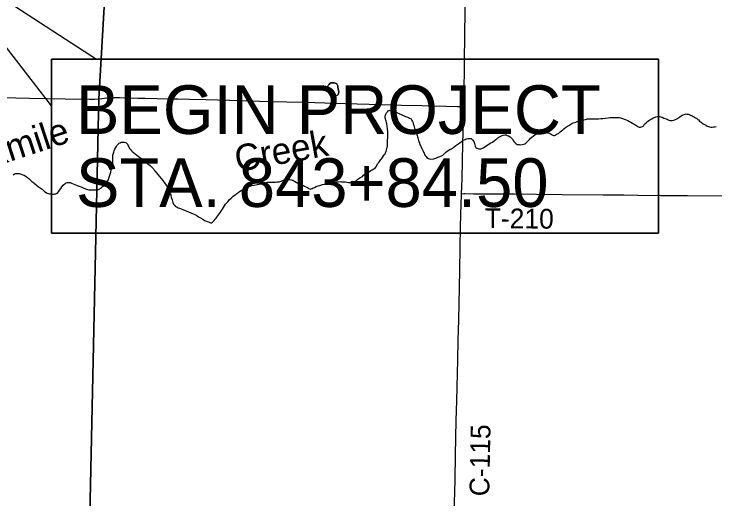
# Model space of a CAD drawing. Extents: x 0 to 64.8, y -5 to 22.
# Drawn here: x 5.41 to 7.424, y 15.884 to 17.279 of the extents above; entities that cross this region are included whole.
import ezdxf

# ---------------------------------------------------------------- set-up
doc = ezdxf.new("R2010")
doc.units = 0
for name, color, linetype in [('GM_X_County_Road', 7, 'Continuous'), ('GM_X_County_Road_Text', 7, 'Continuous'), ('GM_X_Minor_Lake', 7, 'Continuous'), ('GM_X_Minor_Lake_Text', 7, 'Continuous'), ('GM_X_Minor_River', 7, 'Continuous'), ('GM_X_Township', 7, 'Continuous'), ('GM_X_Township_Road', 7, 'Continuous'), ('GM_X_Township_Road_Text', 7, 'Continuous'), ('SH_Masking', 7, 'Continuous'), ('SH_Text', 7, 'Continuous')]:
    doc.layers.add(name, color=color, linetype=linetype)

msp = doc.modelspace()

# ---------------------------------------------------------------- linework, layer by layer
at = {"layer": 'GM_X_County_Road'}
for points in [[(6.7028, 17.0128), (6.7036, 17.0514), (6.7049, 17.1322), (6.7058, 17.2286), (6.7073, 17.328), (6.7091, 17.4368), (6.7108, 17.527), (6.7132, 17.6357), (6.7159, 17.7569), (6.7163, 17.7699)], [(6.6963, 16.7621), (6.6973, 16.8059), (6.6987, 16.8556), (6.6998, 16.9054), (6.7017, 16.9706), (6.7028, 17.011), (6.7028, 17.0128)], [(6.6739, 15.7722), (6.6742, 15.7853), (6.6747, 15.8052), (6.6752, 15.8394), (6.6773, 15.9389), (6.6787, 16.0104), (6.6808, 16.1098), (6.682, 16.1658), (6.685, 16.2838), (6.6863, 16.3398), (6.6877, 16.3988), (6.6897, 16.4921), (6.6909, 16.5418), (6.6922, 16.6071), (6.6934, 16.6661), (6.6942, 16.7034), (6.6962, 16.7593), (6.6963, 16.7621)]]:
    msp.add_lwpolyline(points, dxfattribs=at)
at = {"layer": 'GM_X_Minor_Lake'}
for points in [[(6.3413, 17.0651), (6.3406, 17.0674), (6.3403, 17.0701), (6.34, 17.072), (6.3393, 17.0747), (6.3386, 17.0766), (6.3371, 17.0785), (6.3352, 17.0793), (6.3329, 17.0805), (6.3299, 17.0809), (6.3265, 17.0814), (6.3242, 17.0811), (6.3219, 17.0811), (6.32, 17.0808), (6.3177, 17.0793), (6.315, 17.0767), (6.3126, 17.0737), (6.3118, 17.0715), (6.311, 17.0692), (6.3114, 17.0704), (6.311, 17.0692)], [(6.311, 17.0692), (6.3114, 17.0704), (6.311, 17.0692), (6.3118, 17.0715), (6.3126, 17.0737), (6.315, 17.0767), (6.3177, 17.0793), (6.32, 17.0808), (6.3219, 17.0811), (6.3242, 17.0811), (6.3265, 17.0814), (6.3299, 17.0809), (6.3329, 17.0805), (6.3352, 17.0793), (6.3371, 17.0785), (6.3386, 17.0766), (6.3393, 17.0747), (6.34, 17.072), (6.3403, 17.0701), (6.3406, 17.0674), (6.3413, 17.0651), (6.3417, 17.0632), (6.3424, 17.0598), (6.3427, 17.0579), (6.343, 17.056), (6.3434, 17.0533), (6.3425, 17.051), (6.341, 17.0476), (6.339, 17.0458), (6.3344, 17.044), (6.3317, 17.0429), (6.3291, 17.0426), (6.3271, 17.0423), (6.3241, 17.0427), (6.3218, 17.0431), (6.3192, 17.0447), (6.317, 17.0471), (6.3159, 17.049), (6.3148, 17.052), (6.3137, 17.0551), (6.313, 17.0578), (6.311, 17.0692)], [(6.311, 17.0692), (6.313, 17.0578), (6.3137, 17.0551), (6.3148, 17.052), (6.3159, 17.049), (6.317, 17.0471), (6.3192, 17.0447), (6.3218, 17.0431), (6.3241, 17.0427), (6.3271, 17.0423), (6.3291, 17.0426), (6.3317, 17.0429), (6.3344, 17.044), (6.339, 17.0458), (6.341, 17.0476), (6.3425, 17.051), (6.3434, 17.0533), (6.343, 17.056), (6.3427, 17.0579), (6.3424, 17.0598), (6.3417, 17.0632), (6.3413, 17.0651)]]:
    msp.add_lwpolyline(points, dxfattribs=at)
at = {"layer": 'GM_X_Minor_River'}
for points in [[(6.3763, 16.7946), (6.3809, 16.7945), (6.3843, 16.7944), (6.387, 16.7959), (6.3897, 16.7973), (6.3928, 16.7995), (6.3974, 16.8036), (6.4032, 16.8077), (6.4078, 16.8098), (6.4109, 16.812), (6.414, 16.815), (6.4179, 16.818), (6.4225, 16.8209), (6.4268, 16.8235), (6.4314, 16.826), (6.4352, 16.8286), (6.4395, 16.8311), (6.4437, 16.8341), (6.4472, 16.8359), (6.4492, 16.8385), (6.4555, 16.8486), (6.4578, 16.8516), (6.4598, 16.8546), (6.4617, 16.8572), (6.4641, 16.8606), (6.4668, 16.8636), (6.4692, 16.8666), (6.4719, 16.8707), (6.4739, 16.8744), (6.4763, 16.877), (6.4775, 16.8793), (6.4783, 16.8816), (6.4795, 16.8849), (6.4803, 16.8883), (6.4815, 16.8921), (6.4824, 16.8959), (6.4828, 16.8993), (6.4829, 16.9031), (6.4834, 16.9088), (6.4835, 16.913), (6.4836, 16.9171), (6.4841, 16.9217), (6.4842, 16.9266), (6.4843, 16.9319), (6.4841, 16.9369), (6.4838, 16.9422), (6.4835, 16.9468), (6.4829, 16.951), (6.4826, 16.9544), (6.4823, 16.9574), (6.4816, 16.9613), (6.4809, 16.9639), (6.4802, 16.967), (6.4791, 16.9704), (6.4784, 16.9739), (6.4774, 16.9773), (6.4767, 16.9807), (6.4764, 16.983), (6.4768, 16.9857), (6.4776, 16.9883), (6.4785, 16.991), (6.4804, 16.9947), (6.4828, 16.9977), (6.4847, 17.0003), (6.4878, 17.0018), (6.4909, 17.0025), (6.4939, 17.0016), (6.4988, 16.9996), (6.506, 16.9972), (6.5139, 16.994), (6.5346, 16.9844), (6.5402, 16.9823), (6.5432, 16.9811), (6.5463, 16.9799), (6.5489, 16.9787), (6.5515, 16.9779), (6.5522, 16.9756), (6.5533, 16.9725), (6.5548, 16.9695), (6.5559, 16.9675), (6.5566, 16.9656), (6.5573, 16.9633), (6.558, 16.9614), (6.5591, 16.9584), (6.5601, 16.9542), (6.5608, 16.9507), (6.5622, 16.9465), (6.564, 16.9423), (6.5651, 16.9388), (6.5658, 16.9358), (6.5672, 16.9327), (6.5683, 16.9293), (6.5694, 16.9258), (6.5704, 16.9224), (6.5715, 16.9189), (6.5722, 16.9155), (6.5732, 16.9117), (6.5747, 16.9082), (6.5765, 16.9029), (6.5787, 16.899), (6.5801, 16.8952)], [(6.9294, 16.9393), (6.9339, 16.9388), (6.9483, 16.9359), (6.9513, 16.9346), (6.9539, 16.9331), (6.9566, 16.9319), (6.9585, 16.9307), (6.9603, 16.9299), (6.963, 16.9294), (6.9664, 16.9309), (6.9684, 16.9324), (6.9711, 16.9342), (6.9742, 16.9356), (6.9761, 16.9375), (6.9792, 16.9401), (6.9831, 16.943), (6.9869, 16.9456), (6.9904, 16.9486), (6.9947, 16.9527), (7.0005, 16.9563), (7.0043, 16.9585), (7.007, 16.96), (7.0097, 16.9622), (7.0132, 16.9644), (7.017, 16.9662), (7.0209, 16.9673), (7.0247, 16.9683), (7.0285, 16.9697), (7.0328, 16.9712), (7.0373, 16.9726), (7.0427, 16.974), (7.0473, 16.975), (7.0523, 16.976), (7.058, 16.9771), (7.0637, 16.9773), (7.0698, 16.9772), (7.0762, 16.9774), (7.0831, 16.9776), (7.0899, 16.9779), (7.0964, 16.9781), (7.1025, 16.9787), (7.109, 16.9797), (7.1174, 16.9803), (7.1235, 16.9809), (7.1292, 16.9815), (7.1349, 16.9814), (7.1398, 16.9817), (7.1448, 16.9816), (7.1489, 16.9811), (7.1527, 16.9802), (7.1561, 16.9794), (7.1693, 16.9745), (7.1742, 16.9725), (7.1787, 16.9701), (7.1829, 16.9678), (7.187, 16.9654), (7.1907, 16.963), (7.1941, 16.9611), (7.1967, 16.9591), (7.1994, 16.9571), (7.202, 16.9556), (7.2042, 16.9544), (7.2065, 16.9539), (7.2099, 16.9539), (7.2126, 16.9546), (7.216, 16.9553), (7.2183, 16.956), (7.2195, 16.9582), (7.2223, 16.9623), (7.2262, 16.966), (7.23, 16.9694), (7.2339, 16.9723), (7.2374, 16.9749), (7.2428, 16.9778), (7.2466, 16.98), (7.2509, 16.9818), (7.2543, 16.9833), (7.2578, 16.9843), (7.26, 16.9846), (7.262, 16.985), (7.2654, 16.9841), (7.2688, 16.9833), (7.2725, 16.9821), (7.2774, 16.9793), (7.2842, 16.9773), (7.2884, 16.9753), (7.2914, 16.9737), (7.2944, 16.9729), (7.2978, 16.9724), (7.3016, 16.9727), (7.3062, 16.9741), (7.3108, 16.9759), (7.315, 16.9777), (7.3177, 16.9795), (7.3204, 16.9814), (7.3231, 16.9832), (7.327, 16.9866), (7.3297, 16.9884), (7.3385, 16.9912), (7.3412, 16.9916), (7.3438, 16.9911)], [(7.3438, 16.9911), (7.3473, 16.9907), (7.3507, 16.9898), (7.3537, 16.9882), (7.3567, 16.987), (7.3589, 16.9858), (7.3619, 16.9842), (7.3653, 16.9823), (7.3683, 16.9807), (7.3709, 16.9791), (7.3732, 16.9775), (7.3751, 16.9756), (7.3769, 16.9744), (7.3803, 16.9709), (7.3825, 16.9693), (7.3848, 16.9678), (7.3874, 16.9654), (7.3904, 16.9635), (7.3941, 16.9611), (7.3968, 16.9599), (7.3994, 16.9583), (7.402, 16.9568), (7.4054, 16.9555), (7.4088, 16.9543), (7.4122, 16.9539), (7.416, 16.9538), (7.4198, 16.9541), (7.424, 16.9544), (7.4282, 16.955)], [(6.5801, 16.8952), (6.5819, 16.8921), (6.5837, 16.8883), (6.5852, 16.8848), (6.5866, 16.8814), (6.5881, 16.8783), (6.5899, 16.8748), (6.5917, 16.8718), (6.5939, 16.8687), (6.5965, 16.866), (6.6007, 16.8632), (6.6037, 16.862), (6.6063, 16.8612), (6.6166, 16.8625), (6.622, 16.8642), (6.6274, 16.8668), (6.6335, 16.8693), (6.6385, 16.8715), (6.6423, 16.8733), (6.6458, 16.877), (6.6501, 16.8803), (6.6544, 16.8844), (6.659, 16.8873), (6.6636, 16.8899), (6.6671, 16.8913), (6.6698, 16.8928), (6.6721, 16.8939), (6.6752, 16.8968), (6.6798, 16.9005), (6.6856, 16.9046), (6.691, 16.9083), (6.6961, 16.9119), (6.6988, 16.9142), (6.7011, 16.916), (6.7061, 16.9185), (6.7095, 16.9196), (6.7141, 16.9206), (6.7183, 16.9206), (6.721, 16.9209), (6.7233, 16.9208), (6.7266, 16.9177), (6.7285, 16.9158), (6.7303, 16.9134), (6.7318, 16.9115), (6.7325, 16.9092), (6.7336, 16.9061), (6.7339, 16.9031), (6.7349, 16.8993), (6.7375, 16.8954), (6.7397, 16.8931), (6.7424, 16.8919), (6.7454, 16.8911), (6.7488, 16.891), (6.7515, 16.8913), (6.7542, 16.892), (6.758, 16.8942), (6.7626, 16.8968), (6.7785, 16.9078), (6.7846, 16.9107), (6.7916, 16.9159), (6.7978, 16.9203), (6.8005, 16.9225), (6.8028, 16.9243), (6.8093, 16.928), (6.8128, 16.9294), (6.8155, 16.9305), (6.8208, 16.9311), (6.8242, 16.9311), (6.8273, 16.9299), (6.8314, 16.9282), (6.8359, 16.9255), (6.84, 16.922), (6.843, 16.9185), (6.8448, 16.9154), (6.8466, 16.9123), (6.8485, 16.91), (6.85, 16.9081), (6.8533, 16.9053), (6.8556, 16.9038), (6.8586, 16.9033), (6.8624, 16.9032), (6.8662, 16.9031), (6.8704, 16.9038), (6.8742, 16.9045), (6.8777, 16.9059), (6.8807, 16.9078), (6.8835, 16.91), (6.8862, 16.9129), (6.8909, 16.9178), (6.8944, 16.9215), (6.8982, 16.9248), (6.9025, 16.9285), (6.9064, 16.9315), (6.9106, 16.934), (6.9137, 16.9359), (6.9164, 16.9377), (6.9191, 16.9388), (6.921, 16.9395), (6.9237, 16.9402), (6.9263, 16.9401), (6.9294, 16.9393)], [(5.6864, 16.8182), (5.6877, 16.8243), (5.6889, 16.8307), (5.6906, 16.8379), (5.6919, 16.8428), (5.6927, 16.8462), (5.6932, 16.8492), (5.6932, 16.853), (5.6934, 16.8587), (5.6939, 16.8633), (5.694, 16.8686), (5.6941, 16.8728), (5.6949, 16.8754), (5.6957, 16.8784), (5.6965, 16.8814), (5.6978, 16.8852), (5.6994, 16.8901), (5.7018, 16.8946), (5.7038, 16.8976), (5.7061, 16.9014), (5.7089, 16.9043), (5.7123, 16.9073), (5.715, 16.9088), (5.7177, 16.9102), (5.7208, 16.9105), (5.7242, 16.9104), (5.7276, 16.9104), (5.7306, 16.9095), (5.7325, 16.9072), (5.7355, 16.9045), (5.742, 16.8926), (5.7439, 16.8899), (5.7454, 16.8879), (5.7472, 16.8856), (5.7491, 16.8837), (5.7517, 16.8817), (5.7543, 16.8794), (5.7577, 16.8766), (5.7629, 16.8731), (5.7666, 16.87), (5.7707, 16.8672), (5.776, 16.8637), (5.7816, 16.859), (5.7879, 16.8535), (5.7943, 16.8485), (5.8006, 16.843), (5.8055, 16.8387), (5.8084, 16.8356), (5.8103, 16.8333), (5.8121, 16.8302), (5.8155, 16.8267), (5.8192, 16.8221), (5.8232, 16.8174), (5.8277, 16.812), (5.8325, 16.8062), (5.8369, 16.8004), (5.8413, 16.7942), (5.845, 16.7892), (5.8476, 16.7849), (5.8494, 16.7811), (5.8509, 16.778), (5.853, 16.7738), (5.8549, 16.7696), (5.857, 16.7653), (5.8589, 16.7619), (5.8599, 16.7588), (5.8606, 16.7558), (5.8613, 16.7523), (5.8624, 16.7489), (5.8638, 16.7447), (5.8648, 16.7405), (5.8663, 16.7366), (5.8677, 16.7321), (5.8707, 16.7289), (5.8729, 16.7266), (5.8751, 16.7254), (5.8782, 16.7238), (5.8815, 16.7219), (5.8853, 16.7203), (5.8902, 16.7186), (5.906, 16.7122), (5.9109, 16.7102), (5.9181, 16.707), (5.9241, 16.7046), (5.9297, 16.7022), (5.9346, 16.6994), (5.9399, 16.6958), (5.9459, 16.6923), (5.9519, 16.6887), (5.9575, 16.6852), (5.9628, 16.6828), (5.9673, 16.6808), (5.9703, 16.68), (5.9722, 16.6792), (5.9745, 16.6787), (5.9771, 16.6783), (5.9802, 16.6801), (5.9822, 16.6824), (5.9849, 16.6853), (5.988, 16.6891), (5.9903, 16.6917)], [(5.4069, 16.8162), (5.4107, 16.8188), (5.4142, 16.8198), (5.4165, 16.8202), (5.421, 16.8204), (5.4248, 16.82), (5.4305, 16.8183), (5.4346, 16.8167), (5.4384, 16.8151), (5.4414, 16.8135), (5.4444, 16.8119), (5.447, 16.81), (5.4497, 16.808), (5.4523, 16.8057), (5.4553, 16.8029), (5.4582, 16.8002), (5.4612, 16.7975), (5.4661, 16.7936), (5.4739, 16.7866), (5.4765, 16.7846), (5.4791, 16.783), (5.4814, 16.7811), (5.4844, 16.7791), (5.4874, 16.7771), (5.4904, 16.7748), (5.4933, 16.7721), (5.4971, 16.7686), (5.5019, 16.7658), (5.5053, 16.7634), (5.5083, 16.7626), (5.5114, 16.7618), (5.5136, 16.7617), (5.5159, 16.7617), (5.5178, 16.7613), (5.5197, 16.7612), (5.5227, 16.7611), (5.5254, 16.7611), (5.5277, 16.7614), (5.53, 16.7621), (5.5327, 16.7632), (5.535, 16.7639), (5.5373, 16.7673), (5.5401, 16.7718), (5.544, 16.7766), (5.5472, 16.7819), (5.5507, 16.7867), (5.5573, 16.7927), (5.5592, 16.7938), (5.5619, 16.7944), (5.5646, 16.7948), (5.568, 16.7947), (5.5714, 16.7939), (5.5752, 16.7923), (5.5793, 16.7906), (5.5842, 16.7886), (5.5891, 16.7862), (5.5955, 16.7838), (5.6023, 16.7814), (5.6102, 16.7785), (5.6181, 16.7753), (5.6249, 16.7733), (5.6477, 16.7731), (5.6508, 16.7734), (5.6542, 16.7749), (5.6562, 16.7764), (5.6585, 16.7782), (5.6612, 16.7804), (5.6643, 16.783), (5.6674, 16.7856), (5.6701, 16.7878), (5.672, 16.7897), (5.6744, 16.7927), (5.6767, 16.7956), (5.6787, 16.7979), (5.6807, 16.8024), (5.6823, 16.8069), (5.6843, 16.8126), (5.6864, 16.8182)], [(5.9903, 16.6917), (5.9927, 16.6946), (5.9951, 16.6988), (5.9982, 16.7025), (6.0005, 16.7055), (6.0033, 16.7092), (6.0061, 16.7137), (6.0092, 16.7178), (6.0116, 16.7227), (6.0144, 16.7276), (6.0179, 16.7324), (6.0217, 16.7354), (6.0245, 16.7391), (6.0284, 16.744), (6.0335, 16.7492), (6.0397, 16.7547), (6.0451, 16.7588), (6.0482, 16.761), (6.0505, 16.7625), (6.0528, 16.7647), (6.0555, 16.7665), (6.0579, 16.7688), (6.0625, 16.7717), (6.0656, 16.7732), (6.0717, 16.7768), (6.074, 16.7779), (6.076, 16.779), (6.0787, 16.7808), (6.0829, 16.7826), (6.0879, 16.784), (6.0936, 16.7854), (6.0997, 16.7868), (6.1081, 16.7881), (6.1142, 16.7895), (6.1203, 16.7909), (6.1253, 16.7919), (6.1299, 16.7934), (6.1345, 16.794), (6.1383, 16.7951), (6.1421, 16.7954), (6.1455, 16.7953), (6.1493, 16.7952), (6.1528, 16.7951), (6.1573, 16.795), (6.1611, 16.7957), (6.1649, 16.796), (6.1687, 16.7963), (6.1722, 16.7966), (6.1749, 16.7973), (6.1771, 16.798), (6.1791, 16.7987), (6.1825, 16.8005), (6.1844, 16.8012), (6.1867, 16.8016), (6.1894, 16.8019), (6.1917, 16.8022), (6.1944, 16.8025), (6.1982, 16.8028), (6.2016, 16.8027), (6.205, 16.8023), (6.2069, 16.8019), (6.2088, 16.8014), (6.211, 16.8006), (6.2129, 16.7994), (6.2159, 16.7979), (6.2204, 16.7955), (6.2238, 16.7935), (6.2276, 16.7911), (6.2321, 16.7895), (6.2359, 16.7879), (6.2385, 16.7867), (6.2415, 16.7855), (6.2449, 16.7835), (6.2528, 16.7799), (6.2573, 16.7775), (6.2595, 16.7764), (6.2622, 16.7755), (6.2641, 16.7759), (6.2664, 16.777), (6.2695, 16.7788), (6.2733, 16.7802), (6.2779, 16.7824), (6.2837, 16.7845), (6.289, 16.7859), (6.2963, 16.7881), (6.3021, 16.7898), (6.3085, 16.7912), (6.3147, 16.7922), (6.3208, 16.7932), (6.3261, 16.7938), (6.3303, 16.7945), (6.3337, 16.7956), (6.3379, 16.7962), (6.3425, 16.7965), (6.3467, 16.7968), (6.3509, 16.7967), (6.357, 16.7966), (6.3619, 16.7961), (6.3664, 16.7952), (6.371, 16.7947), (6.3763, 16.7946)]]:
    msp.add_lwpolyline(points, dxfattribs=at)
at = {"layer": 'GM_X_Township'}
for points in [[(5.5757, 14.1), (5.6021, 14.7717), (5.6261, 15.7913), (5.6525, 16.9944), (5.6534, 17.0351), (5.683, 17.5492), (5.69, 17.7297), (5.6921, 17.7902), (5.7284, 18.7976), (5.7288, 18.8067), (5.7555, 19.5524), (5.7579, 19.6183), (5.7612, 19.7093), (5.7653, 19.8404), (5.6534, 19.8431), (5.4698, 19.8478), (5.4325, 19.8487), (5.389, 19.8494)], [(5.683, 17.5492), (5.6534, 17.0351), (5.6525, 16.9944), (5.6261, 15.7913), (5.6021, 14.7717), (5.5757, 14.1)]]:
    msp.add_lwpolyline(points, dxfattribs=at)
at = {"layer": 'GM_X_Township_Road'}
for points in [[(5.1644, 17.0434), (5.1703, 17.0432), (5.2045, 17.0424), (5.3355, 17.0402), (5.4539, 17.0373), (5.5568, 17.0351), (5.6253, 17.0342), (5.6409, 17.0344), (5.6534, 17.0351), (5.6616, 17.036)], [(5.6616, 17.036), (5.6755, 17.0376)], [(5.6755, 17.0376), (5.6845, 17.0383), (5.6969, 17.0388), (5.7125, 17.0388), (5.7435, 17.0378), (5.7652, 17.0371), (5.787, 17.0366), (5.8553, 17.0352), (5.8802, 17.035), (5.9143, 17.0341), (5.9609, 17.033), (6.0635, 17.0302), (6.1411, 17.0278), (6.1939, 17.0265), (6.2374, 17.0255), (6.2747, 17.0246), (6.3026, 17.0235), (6.3274, 17.0225), (6.3616, 17.0213), (6.43, 17.0195), (6.461, 17.0188), (6.4952, 17.018), (6.5231, 17.0172), (6.5822, 17.0157), (6.6163, 17.0149), (6.6505, 17.0141), (6.6847, 17.0132), (6.6973, 17.0129), (6.7028, 17.0128)], [(6.6963, 16.7621), (6.7027, 16.7622), (6.7058, 16.7623), (6.7306, 16.7619), (6.7772, 16.7617), (6.8486, 16.7615), (6.9107, 16.7609), (6.9852, 16.7599), (7.1032, 16.759), (7.1622, 16.7584), (7.2025, 16.7577), (7.2678, 16.7573), (7.3454, 16.7567), (7.4509, 16.756), (7.5192, 16.7557), (7.5441, 16.7556), (7.6497, 16.7555), (7.6869, 16.7553), (7.6945, 16.7553)]]:
    msp.add_lwpolyline(points, dxfattribs=at)
at = {"layer": 'SH_Masking'}
msp.add_lwpolyline([(5.5177, 17.149), (7.2622, 17.149), (7.2622, 16.649), (5.5177, 16.649)], close=True, dxfattribs=at)
at = {"layer": 'SH_Text'}
for p, q in [((5.6467, 17.149), (5.5177, 17.149)), ((5.5177, 17.149), (5.5177, 17.0152))]:
    msp.add_line(p, q, dxfattribs=at)
msp.add_lwpolyline([(5.5177, 17.0152), (5.1787, 17.453), (5.6467, 17.149)], dxfattribs=at)
msp.add_lwpolyline([(5.5177, 16.649), (7.2622, 16.649), (7.2622, 17.149), (5.5177, 17.149)], close=True, dxfattribs=at)

# ---------------------------------------------------------------- texts
at = {"layer": 'GM_X_County_Road_Text'}
msp.add_text('C-115', height=0.05682, rotation=88.8981, dxfattribs=at).set_placement((6.7754, 15.891))
at = {"layer": 'GM_X_Minor_Lake_Text'}
for s, rotation, p in [('Sixmile', 18.2, (5.2645, 16.8101)), ('Creek', 10.1924, (6.0511, 16.8244))]:
    msp.add_text(s, height=0.07579, rotation=rotation, dxfattribs=at).set_placement(p)
at = {"layer": 'GM_X_Township_Road_Text'}
msp.add_text('T-210', height=0.05682, rotation=359.4386, dxfattribs=at).set_placement((6.7624, 16.6633))
at = {"layer": 'SH_Text'}
for s, p in [('BEGIN PROJECT', (5.5877, 16.934)), ('STA. 843+84.50', (5.5877, 16.724))]:
    msp.add_text(s, height=0.14, dxfattribs=at).set_placement(p)

doc.saveas('drawing.dxf')
